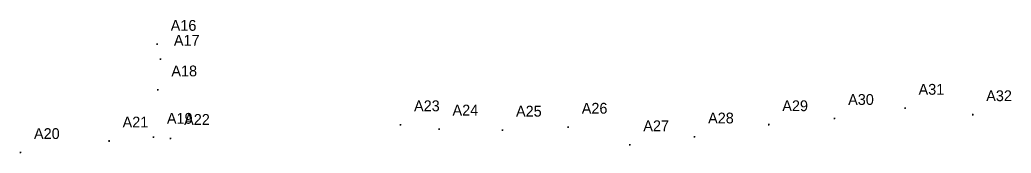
# Model space of a CAD drawing. Extents: x 1727960 to 1749562, y 651707 to 653731.
# Drawn here: x 1749194.5 to 1749561.8, y 652754.8 to 652804.1 of the extents above; entities that cross this region are included whole.
import ezdxf

# ---------------------------------------------------------------- set-up
doc = ezdxf.new("R2010")
doc.units = 0
doc.layers.add('SURVEY - DRAINAGE - Storm Sewer - Points - Locators', color=7, linetype='Continuous')
doc.layers.add('SURVEY - DRAINAGE - Storm Sewer - Points - Numbers', color=7, linetype='Continuous')

msp = doc.modelspace()

# ---------------------------------------------------------------- linework, layer by layer
at = {"layer": 'SURVEY - DRAINAGE - Storm Sewer - Points - Locators'}
for p, q in [((1749245.67, 652795.07), (1749245.17, 652795.07)), ((1749245.42, 652794.82), (1749245.42, 652795.32)), ((1749245.42, 652795.07), (1749245.42, 652795.07)), ((1749245.42, 652795.07), (1749245.42, 652795.07)), ((1749246.6, 652789.31), (1749246.6, 652789.81)), ((1749246.85, 652789.56), (1749246.35, 652789.56)), ((1749246.6, 652789.56), (1749246.6, 652789.56)), ((1749246.6, 652789.56), (1749246.6, 652789.56)), ((1749245.92, 652778.21), (1749245.42, 652778.21)), ((1749245.67, 652777.96), (1749245.67, 652778.46)), ((1749245.67, 652778.21), (1749245.67, 652778.21)), ((1749245.67, 652778.21), (1749245.67, 652778.21)), ((1749522.79, 652771.4), (1749522.29, 652771.4)), ((1749522.54, 652771.15), (1749522.54, 652771.65)), ((1749522.54, 652771.4), (1749522.54, 652771.4)), ((1749522.54, 652771.4), (1749522.54, 652771.4)), ((1749496.69, 652767.64), (1749496.19, 652767.64)), ((1749496.44, 652767.39), (1749496.44, 652767.89)), ((1749496.44, 652767.64), (1749496.44, 652767.64)), ((1749496.44, 652767.64), (1749496.44, 652767.64)), ((1749547.85, 652769.02), (1749547.35, 652769.02)), ((1749547.6, 652768.77), (1749547.6, 652769.27)), ((1749547.6, 652769.02), (1749547.6, 652769.02)), ((1749547.6, 652769.02), (1749547.6, 652769.02)), ((1749335.83, 652765.29), (1749335.33, 652765.29)), ((1749335.58, 652765.04), (1749335.58, 652765.54)), ((1749335.58, 652765.29), (1749335.58, 652765.29)), ((1749335.58, 652765.29), (1749335.58, 652765.29)), ((1749349.84, 652763.45), (1749349.84, 652763.95)), ((1749397.98, 652764.39), (1749397.48, 652764.39)), ((1749397.73, 652764.14), (1749397.73, 652764.64)), ((1749397.73, 652764.39), (1749397.73, 652764.39)), ((1749397.73, 652764.39), (1749397.73, 652764.39)), ((1749472.29, 652765.32), (1749471.79, 652765.32)), ((1749472.04, 652765.07), (1749472.04, 652765.57)), ((1749472.04, 652765.32), (1749472.04, 652765.32)), ((1749472.04, 652765.32), (1749472.04, 652765.32)), ((1749244.25, 652760.66), (1749243.75, 652760.66)), ((1749244, 652760.41), (1749244, 652760.91)), ((1749244, 652760.66), (1749244, 652760.66)), ((1749244, 652760.66), (1749244, 652760.66)), ((1749250.64, 652760.24), (1749250.14, 652760.24)), ((1749250.39, 652759.99), (1749250.39, 652760.49)), ((1749250.39, 652760.24), (1749250.39, 652760.24)), ((1749250.39, 652760.24), (1749250.39, 652760.24)), ((1749350.09, 652763.7), (1749349.59, 652763.7)), ((1749349.84, 652763.7), (1749349.84, 652763.7)), ((1749349.84, 652763.7), (1749349.84, 652763.7)), ((1749373.62, 652763.31), (1749373.12, 652763.31)), ((1749373.37, 652763.06), (1749373.37, 652763.56)), ((1749373.37, 652763.31), (1749373.37, 652763.31)), ((1749373.37, 652763.31), (1749373.37, 652763.31)), ((1749444.8, 652760.78), (1749444.3, 652760.78)), ((1749444.55, 652760.53), (1749444.55, 652761.03)), ((1749444.55, 652760.78), (1749444.55, 652760.78)), ((1749444.55, 652760.78), (1749444.55, 652760.78)), ((1749227.83, 652759.27), (1749227.33, 652759.27)), ((1749227.58, 652759.02), (1749227.58, 652759.52)), ((1749227.58, 652759.27), (1749227.58, 652759.27)), ((1749227.58, 652759.27), (1749227.58, 652759.27)), ((1749420.79, 652757.91), (1749420.29, 652757.91)), ((1749420.54, 652757.66), (1749420.54, 652758.16)), ((1749420.54, 652757.91), (1749420.54, 652757.91)), ((1749420.54, 652757.91), (1749420.54, 652757.91)), ((1749195.01, 652755.02), (1749194.51, 652755.02)), ((1749194.76, 652754.77), (1749194.76, 652755.27)), ((1749194.76, 652755.02), (1749194.76, 652755.02)), ((1749194.76, 652755.02), (1749194.76, 652755.02))]:
    msp.add_line(p, q, dxfattribs=at)

# ---------------------------------------------------------------- texts
at = {"layer": 'SURVEY - DRAINAGE - Storm Sewer - Points - Numbers'}
for s, p in [('A16', (1749250.42, 652800.07)), ('A17', (1749251.6, 652794.56)), ('A18', (1749250.67, 652783.21)), ('A31', (1749527.54, 652776.4)), ('A30', (1749501.44, 652772.64)), ('A32', (1749552.6, 652774.02)), ('A23', (1749340.58, 652770.29)), ('A24', (1749354.84, 652768.7)), ('A25', (1749378.37, 652768.31)), ('A26', (1749402.73, 652769.39)), ('A29', (1749477.04, 652770.32)), ('A21', (1749232.58, 652764.27)), ('A19', (1749249, 652765.66)), ('A22', (1749255.39, 652765.24)), ('A28', (1749449.55, 652765.78)), ('A20', (1749199.76, 652760.02)), ('A27', (1749425.54, 652762.91))]:
    msp.add_text(s, height=4, dxfattribs=at).set_placement(p)

doc.saveas('drawing.dxf')
